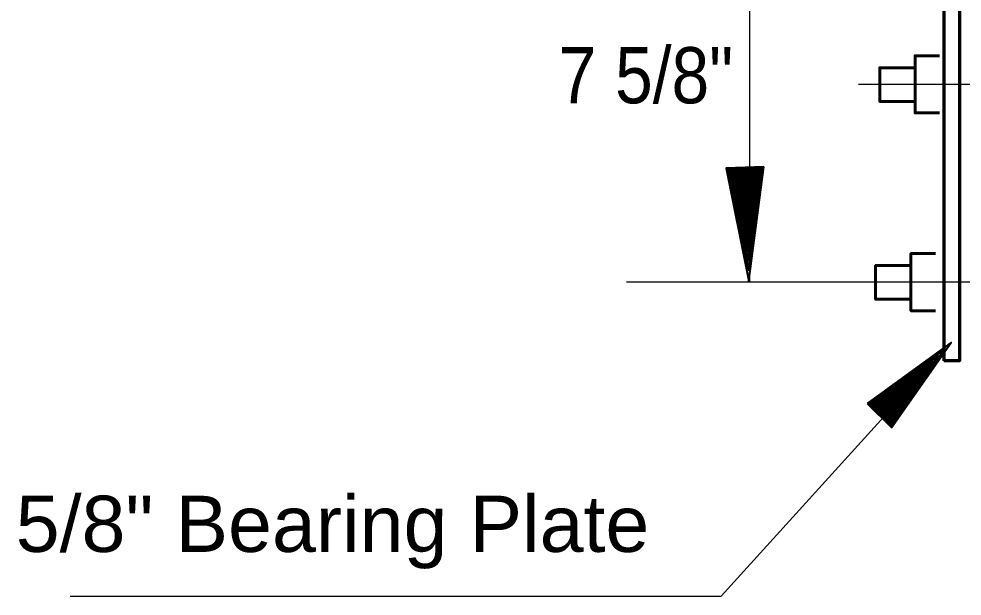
# Model space of a CAD drawing. Extents: x 856.9 to 891.7, y -2278.5 to -2254.7.
# Drawn here: x 861.987 to 864.144, y -2261.29 to -2259.969 of the extents above; entities that cross this region are included whole.
import ezdxf

# ---------------------------------------------------------------- set-up
doc = ezdxf.new("R2010")
doc.units = 0
doc.header["$LTSCALE"] = 0.051
doc.layers.add('1', color=7, linetype='Continuous', lineweight=70)
doc.layers.add('3', color=7, linetype='Continuous', lineweight=40)

msp = doc.modelspace()

# ---------------------------------------------------------------- hatches: boundary and pattern name
at = {"layer": '3'}
for points in [[(863.69117, -2260.30725), (863.6045, -2260.31017), (863.65667, -2260.56858), (863.65667, -2260.56858)], [(863.68683, -2260.3085), (863.60883, -2260.31125), (863.65583, -2260.54383), (863.65583, -2260.54383)], [(863.68292, -2260.30975), (863.61283, -2260.31208), (863.65508, -2260.52142), (863.65508, -2260.52142)], [(863.6795, -2260.31075), (863.61642, -2260.31292), (863.65442, -2260.50142), (863.65442, -2260.50142)], [(863.6765, -2260.31167), (863.61967, -2260.31358), (863.65383, -2260.48333), (863.65383, -2260.48333)], [(863.67358, -2260.31275), (863.6225, -2260.31433), (863.65333, -2260.46708), (863.65333, -2260.46708)], [(863.671, -2260.31342), (863.62508, -2260.31492), (863.65283, -2260.45233), (863.65283, -2260.45233)], [(863.66883, -2260.31425), (863.62733, -2260.3155), (863.65233, -2260.43908), (863.65233, -2260.43908)], [(863.66683, -2260.31467), (863.62942, -2260.316), (863.65183, -2260.42733), (863.65183, -2260.42733)], [(863.66483, -2260.31542), (863.63117, -2260.31658), (863.6515, -2260.4165), (863.6515, -2260.4165)], [(863.66333, -2260.31583), (863.633, -2260.31692), (863.65125, -2260.40692), (863.65125, -2260.40692)], [(863.66175, -2260.31633), (863.63458, -2260.31733), (863.65083, -2260.39833), (863.65083, -2260.39833)], [(863.66042, -2260.31675), (863.63592, -2260.31758), (863.65058, -2260.39042), (863.65058, -2260.39042)], [(863.65917, -2260.31733), (863.63708, -2260.31783), (863.65042, -2260.3835), (863.65042, -2260.3835)], [(863.65808, -2260.3175), (863.63825, -2260.31817), (863.65025, -2260.37725), (863.65025, -2260.37725)], [(863.65708, -2260.31792), (863.63925, -2260.31833), (863.64992, -2260.37158), (863.64992, -2260.37158)], [(863.65617, -2260.31808), (863.64008, -2260.31867), (863.64975, -2260.3665), (863.64975, -2260.3665)], [(863.65533, -2260.31825), (863.64092, -2260.31883), (863.64958, -2260.36192), (863.64958, -2260.36192)], [(863.65492, -2260.31867), (863.64175, -2260.31892), (863.64958, -2260.35783), (863.64958, -2260.35783)], [(863.65433, -2260.31883), (863.6425, -2260.31925), (863.6495, -2260.35417), (863.6495, -2260.35417)], [(863.65383, -2260.31917), (863.64325, -2260.31958), (863.64967, -2260.35092), (863.64967, -2260.35092)], [(863.65325, -2260.31917), (863.64383, -2260.31958), (863.6495, -2260.34783), (863.6495, -2260.34783)], [(863.65275, -2260.31933), (863.64425, -2260.31967), (863.64925, -2260.34508), (863.64925, -2260.34508)], [(863.65233, -2260.31958), (863.64475, -2260.31975), (863.64933, -2260.34275), (863.64933, -2260.34275)], [(863.927, -2260.84875), (863.98258, -2260.90358), (864.11933, -2260.70958), (864.11933, -2260.70958)], [(863.93058, -2260.85067), (863.9805, -2260.90008), (864.10367, -2260.72558), (864.10367, -2260.72558)], [(863.93383, -2260.8525), (863.97867, -2260.89692), (864.0895, -2260.73983), (864.0895, -2260.73983)], [(863.93658, -2260.85408), (863.97692, -2260.894), (864.07675, -2260.75267), (864.07675, -2260.75267)], [(863.939, -2260.85558), (863.9755, -2260.89142), (864.06525, -2260.76425), (864.06525, -2260.76425)], [(863.9415, -2260.85675), (863.97425, -2260.88917), (864.055, -2260.77467), (864.055, -2260.77467)], [(863.94358, -2260.85808), (863.973, -2260.88725), (864.04575, -2260.78408), (864.04575, -2260.78408)], [(863.9455, -2260.85892), (863.97183, -2260.88533), (864.03725, -2260.79258), (864.03725, -2260.79258)], [(863.94692, -2260.86), (863.97108, -2260.88358), (864.02983, -2260.80017), (864.02983, -2260.80017)], [(863.94858, -2260.86083), (863.97033, -2260.88217), (864.02308, -2260.807), (864.02308, -2260.807)], [(863.95, -2260.86158), (863.96933, -2260.88067), (864.017, -2260.81325), (864.017, -2260.81325)], [(863.95125, -2260.86242), (863.96858, -2260.8795), (864.01158, -2260.81883), (864.01158, -2260.81883)], [(863.95233, -2260.86292), (863.968, -2260.87842), (864.0065, -2260.82383), (864.0065, -2260.82383)], [(863.95342, -2260.86342), (863.96742, -2260.8775), (864.00217, -2260.82808), (864.00217, -2260.82808)], [(863.95425, -2260.86392), (863.96692, -2260.87658), (863.99808, -2260.83217), (863.99808, -2260.83217)], [(863.955, -2260.86442), (863.9665, -2260.87583), (863.99467, -2260.83592), (863.99467, -2260.83592)], [(863.95583, -2260.86492), (863.96617, -2260.87517), (863.99142, -2260.83917), (863.99142, -2260.83917)], [(863.95642, -2260.86533), (863.96567, -2260.87442), (863.98858, -2260.84208), (863.98858, -2260.84208)], [(863.957, -2260.86533), (863.96525, -2260.87383), (863.98583, -2260.84458), (863.98583, -2260.84458)], [(863.9575, -2260.86567), (863.965, -2260.87317), (863.98358, -2260.84683), (863.98358, -2260.84683)], [(863.95792, -2260.86567), (863.96475, -2260.87242), (863.98125, -2260.84883), (863.98125, -2260.84883)], [(863.95833, -2260.86617), (863.96442, -2260.87208), (863.97933, -2260.85083), (863.97933, -2260.85083)], [(863.95875, -2260.86633), (863.96425, -2260.87167), (863.97783, -2260.85267), (863.97783, -2260.85267)], [(863.95908, -2260.8665), (863.964, -2260.87133), (863.97617, -2260.85408), (863.97617, -2260.85408)]]:
    msp.add_hatch(color=256, dxfattribs=at).paths.add_polyline_path(points)

# ---------------------------------------------------------------- linework, layer by layer
at = {"layer": '1', "lineweight": 25}
for p, q in [((863.65917, -2260.57142), (863.65917, -2258.18292)), ((866.58492, -2260.11883), (863.90775, -2260.11883)), ((865.83625, -2260.57142), (863.37692, -2260.57142)), ((864.01067, -2260.82967), (863.59292, -2261.28958)), ((862.10392, -2261.28958), (863.59292, -2261.28958))]:
    msp.add_line(p, q, dxfattribs=at)
at = {"layer": '1'}
msp.add_line((864.10225, -2258.59408), (864.10225, -2260.75108), dxfattribs=at)
msp.add_lwpolyline([(864.13817, -2258.59408), (864.13817, -2260.75108), (864.10225, -2260.75108)], dxfattribs=at)
at = {"layer": '1', "lineweight": 60}
for points in [[(864.09267, -2260.05317), (864.03692, -2260.05317), (864.03692, -2260.184), (864.09267, -2260.184)], [(864.03692, -2260.08067), (863.95592, -2260.08067), (863.95592, -2260.15775), (864.03692, -2260.15775)], [(864.08317, -2260.50567), (864.02742, -2260.50567), (864.02742, -2260.6365), (864.08317, -2260.6365)], [(864.02742, -2260.53317), (863.94642, -2260.53317), (863.94642, -2260.61025), (864.02742, -2260.61025)]]:
    msp.add_lwpolyline(points, dxfattribs=at)
at = {"layer": '3'}
for points in [[(863.69117, -2260.30725), (863.6045, -2260.31017), (863.65667, -2260.56858), (863.65667, -2260.56858)], [(863.68683, -2260.3085), (863.60883, -2260.31125), (863.65583, -2260.54383), (863.65583, -2260.54383)], [(863.68292, -2260.30975), (863.61283, -2260.31208), (863.65508, -2260.52142), (863.65508, -2260.52142)], [(863.6795, -2260.31075), (863.61642, -2260.31292), (863.65442, -2260.50142), (863.65442, -2260.50142)], [(863.6765, -2260.31167), (863.61967, -2260.31358), (863.65383, -2260.48333), (863.65383, -2260.48333)], [(863.67358, -2260.31275), (863.6225, -2260.31433), (863.65333, -2260.46708), (863.65333, -2260.46708)], [(863.671, -2260.31342), (863.62508, -2260.31492), (863.65283, -2260.45233), (863.65283, -2260.45233)], [(863.66883, -2260.31425), (863.62733, -2260.3155), (863.65233, -2260.43908), (863.65233, -2260.43908)], [(863.66683, -2260.31467), (863.62942, -2260.316), (863.65183, -2260.42733), (863.65183, -2260.42733)], [(863.66483, -2260.31542), (863.63117, -2260.31658), (863.6515, -2260.4165), (863.6515, -2260.4165)], [(863.66333, -2260.31583), (863.633, -2260.31692), (863.65125, -2260.40692), (863.65125, -2260.40692)], [(863.66175, -2260.31633), (863.63458, -2260.31733), (863.65083, -2260.39833), (863.65083, -2260.39833)], [(863.66042, -2260.31675), (863.63592, -2260.31758), (863.65058, -2260.39042), (863.65058, -2260.39042)], [(863.65917, -2260.31733), (863.63708, -2260.31783), (863.65042, -2260.3835), (863.65042, -2260.3835)], [(863.65808, -2260.3175), (863.63825, -2260.31817), (863.65025, -2260.37725), (863.65025, -2260.37725)], [(863.65708, -2260.31792), (863.63925, -2260.31833), (863.64992, -2260.37158), (863.64992, -2260.37158)], [(863.65617, -2260.31808), (863.64008, -2260.31867), (863.64975, -2260.3665), (863.64975, -2260.3665)], [(863.65533, -2260.31825), (863.64092, -2260.31883), (863.64958, -2260.36192), (863.64958, -2260.36192)], [(863.65492, -2260.31867), (863.64175, -2260.31892), (863.64958, -2260.35783), (863.64958, -2260.35783)], [(863.65433, -2260.31883), (863.6425, -2260.31925), (863.6495, -2260.35417), (863.6495, -2260.35417)], [(863.65383, -2260.31917), (863.64325, -2260.31958), (863.64967, -2260.35092), (863.64967, -2260.35092)], [(863.65325, -2260.31917), (863.64383, -2260.31958), (863.6495, -2260.34783), (863.6495, -2260.34783)], [(863.65275, -2260.31933), (863.64425, -2260.31967), (863.64925, -2260.34508), (863.64925, -2260.34508)], [(863.65233, -2260.31958), (863.64475, -2260.31975), (863.64933, -2260.34275), (863.64933, -2260.34275)], [(863.927, -2260.84875), (863.98258, -2260.90358), (864.11933, -2260.70958), (864.11933, -2260.70958)], [(863.93058, -2260.85067), (863.9805, -2260.90008), (864.10367, -2260.72558), (864.10367, -2260.72558)], [(863.93383, -2260.8525), (863.97867, -2260.89692), (864.0895, -2260.73983), (864.0895, -2260.73983)], [(863.93658, -2260.85408), (863.97692, -2260.894), (864.07675, -2260.75267), (864.07675, -2260.75267)], [(863.939, -2260.85558), (863.9755, -2260.89142), (864.06525, -2260.76425), (864.06525, -2260.76425)], [(863.9415, -2260.85675), (863.97425, -2260.88917), (864.055, -2260.77467), (864.055, -2260.77467)], [(863.94358, -2260.85808), (863.973, -2260.88725), (864.04575, -2260.78408), (864.04575, -2260.78408)], [(863.9455, -2260.85892), (863.97183, -2260.88533), (864.03725, -2260.79258), (864.03725, -2260.79258)], [(863.94692, -2260.86), (863.97108, -2260.88358), (864.02983, -2260.80017), (864.02983, -2260.80017)], [(863.94858, -2260.86083), (863.97033, -2260.88217), (864.02308, -2260.807), (864.02308, -2260.807)], [(863.95, -2260.86158), (863.96933, -2260.88067), (864.017, -2260.81325), (864.017, -2260.81325)], [(863.95125, -2260.86242), (863.96858, -2260.8795), (864.01158, -2260.81883), (864.01158, -2260.81883)], [(863.95233, -2260.86292), (863.968, -2260.87842), (864.0065, -2260.82383), (864.0065, -2260.82383)], [(863.95342, -2260.86342), (863.96742, -2260.8775), (864.00217, -2260.82808), (864.00217, -2260.82808)], [(863.95425, -2260.86392), (863.96692, -2260.87658), (863.99808, -2260.83217), (863.99808, -2260.83217)], [(863.955, -2260.86442), (863.9665, -2260.87583), (863.99467, -2260.83592), (863.99467, -2260.83592)], [(863.95583, -2260.86492), (863.96617, -2260.87517), (863.99142, -2260.83917), (863.99142, -2260.83917)], [(863.95642, -2260.86533), (863.96567, -2260.87442), (863.98858, -2260.84208), (863.98858, -2260.84208)], [(863.957, -2260.86533), (863.96525, -2260.87383), (863.98583, -2260.84458), (863.98583, -2260.84458)], [(863.9575, -2260.86567), (863.965, -2260.87317), (863.98358, -2260.84683), (863.98358, -2260.84683)], [(863.95792, -2260.86567), (863.96475, -2260.87242), (863.98125, -2260.84883), (863.98125, -2260.84883)], [(863.95833, -2260.86617), (863.96442, -2260.87208), (863.97933, -2260.85083), (863.97933, -2260.85083)], [(863.95875, -2260.86633), (863.96425, -2260.87167), (863.97783, -2260.85267), (863.97783, -2260.85267)], [(863.95908, -2260.8665), (863.964, -2260.87133), (863.97617, -2260.85408), (863.97617, -2260.85408)]]:
    msp.add_lwpolyline(points, close=True, dxfattribs=at)

# ---------------------------------------------------------------- texts
at = {"layer": '1'}
for s, width, p in [('7 5/8"', 0.9, (863.22158, -2260.16208)), ('5/8" Bearing Plate', 1.05, (861.97958, -2261.18842))]:
    msp.add_text(s, height=0.1286, dxfattribs=dict(at, width=width)).set_placement(p)

doc.saveas('drawing.dxf')
